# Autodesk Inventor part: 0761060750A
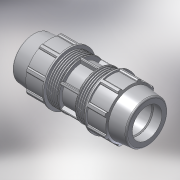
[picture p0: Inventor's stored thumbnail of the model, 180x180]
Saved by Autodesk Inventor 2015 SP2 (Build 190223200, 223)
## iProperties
Created: 2017-02
Part Number: 0761060750A
Material: PVC-Piping
Description: PLASSON REPAIR COUPLER 75
Document SubType Name: Modeling
Designer: KIM
Mass: 2387.75 g
Surface Area: 2478.17 cm^2
Volume: 1705.54 cm^3
Density: 1.4 g/cm^3
Appearance: Smooth - White
Author: KIM
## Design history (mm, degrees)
derived "87610.ipt"
feature "Solid1::87610.ipt"
tag "TaggingFeature1"
body "Solid1"
other parameters: "d1" = 278, "d2" = 75, "d4" = 23.16667, "d5" = 39.71429, "d7" = 134, "d8" = 100.5, "d9" = 39.71429, "d11" = 3.97143, "d12" = 107.2, "d13" = 120 deg, "d14" = 105, "d15" = 6 deg, "d16" = 120.6, "d18" = 3.75, "d19" = 35 deg, "d20" = 17.5 deg, "d21" = 124.62, "d23" = 0, "d25" = 360 deg, "d27" = 2.68, "d33" = 1.5, "d34" = 6.7, "d36" = 0, "d37" = 1.5, "d38" = 1.5, "d40" = 360 deg, "d42" = 50.04, "d46" = 2.25, "d50" = 3.475, "d51" = 0, "d53" = 2.54171, "d54" = 2.54171, "d57" = 5.08343, "d62" = 118.188, "d_" = 75, "E_" = 134, "H_" = 278, "l_" = 143, "d52" = 25.41714
